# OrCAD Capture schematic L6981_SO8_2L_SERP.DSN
size Custom
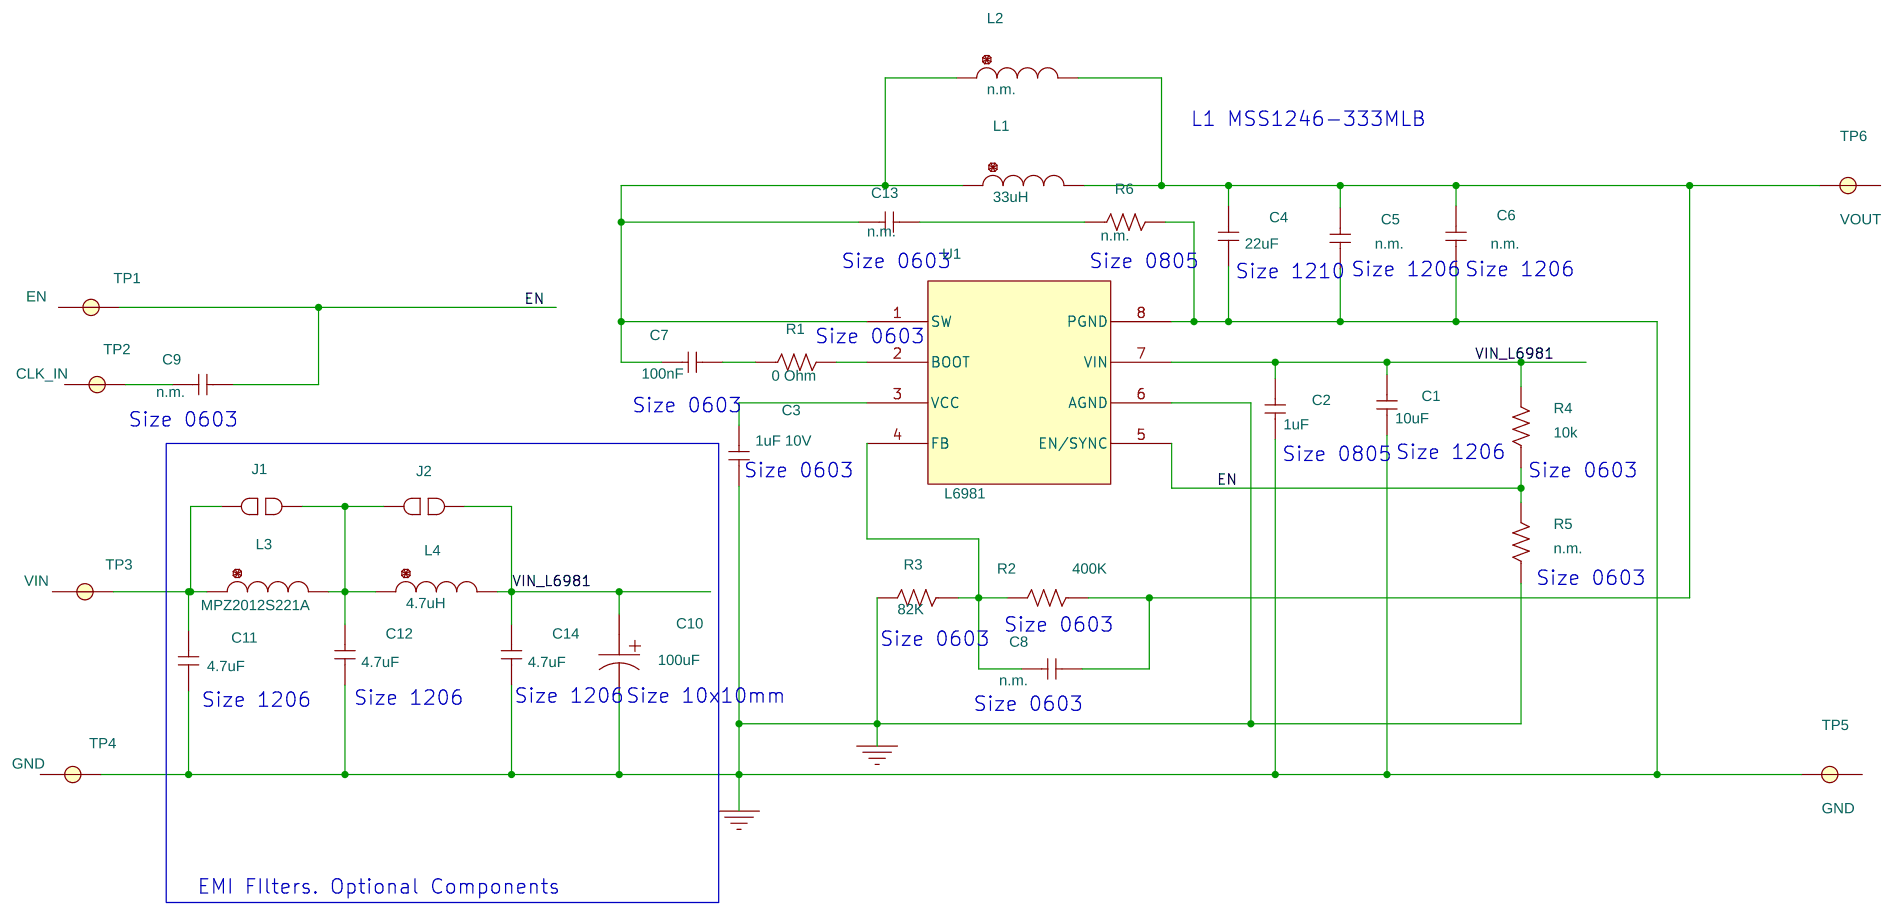
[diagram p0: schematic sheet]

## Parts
C1  10uF  [c1206]
C2  1uF  [c0805]
C3  1uF 10V  [c0603]
C4  22uF  [c1210]
C5  n.m.  [c1206]
C6  n.m.  [c1206]
C7  100nF  [c0603]
C8  n.m.  [c0603]
C9  n.m.  [c0603]
C10  100uF  [el_smd_all_G]
C11  4.7uF  [c1206]
C12  4.7uF  [c1206]
C13  n.m.  [c0603]
C14  4.7uF  [c1206]
J1  CUT 3  [PONT2_0603_no_paste]
J2  CUT 3  [PONT2_0603_no_paste]
L1  33uH  [ind_MSS1038]
L2  n.m.  [ind_XAL4040]
L3  MPZ2012S221A  [ind_mpz2012]
L4  4.7uH  [ind_XAL4040]
R1  0 Ohm  [0603]
R2  400K  [0603]
R3  82K  [0603]
R4  10k  [0603]
R5  n.m.  [0603]
R6  n.m.  [0805]
TP1  EN  [tp_torretta_13mm_f1_5]
TP2  CLK_IN  [tp_torretta_13mm_f1_5]
TP3  VIN  [tp_torretta_13mm_f1_5]
TP4  GND  [tp_torretta_13mm_f1_5]
TP5  GND  [tp_torretta_13mm_f1_5]
TP6  VOUT  [tp_torretta_13mm_f1_5]
U1  L6981  [SO8]

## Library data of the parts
C1 = C: Input capacitor; Manufacturer: TDK; Manufacturer Code: CGA5L3X5R1H106K160AB; TOLERANCE: 10%; VOLTAGE: 50
C2 = C: Input capacitor; Manufacturer: TDK; Manufacturer Code: CGA4J3X7R1H105K125AB; TOLERANCE: 10%; VOLTAGE: 50
C3 = C: Vcc capacitor; Manufacturer: Any; TOLERANCE: 10%; VOLTAGE: 10
C4 = C: Vout capacitor; Manufacturer: TDK; Manufacturer Code: CGA6P1X7R1C226M250AC; TOLERANCE: 20%; VOLTAGE: 16
C5 C6 = C: Vout capacitor; Assembly Information: Not Mounted
C7 = C: Boot capacitor; TOLERANCE: 10%; VOLTAGE: 50
C8 = C: Feed forward capacitor; Assembly Information: Not Mounted; Manufacturer: Any
C9 = C: Extern Sync. Capacitor; Assembly Information: Not Mounted; Manufacturer: Any
C10 = CAPACITOR_POL_1: El. Pi filter capacitor; Manufacturer: Panasonic; Manufacturer Code: EEHZA1H101P; TOLERANCE: 20%; VOLTAGE: 50
C11 C12 C14 = C: PI filter capacitor; Manufacturer: Murata; Manufacturer Code: GRM31CR71H475KA12L; TOLERANCE: 10%; VOLTAGE: 50
C13 = C: Snubber capacitor; Assembly Information: Not Mounted; Manufacturer: Any
J1 = CUT_3_16: Pi filter ferrite/short selector
J2 = CUT_3_16: Pi filter inductor/short selector
L1 = L: Main Inductor; Manufacturer: Coilcraft; Manufacturer Code: MSS1038T-333ML; TOLERANCE: 20%
L2 = L: Main inductor; Assembly Information: Not Mounted; Manufacturer: Coilcraft; Manufacturer Code: XAL4040
L3 = L: Pi filter ferrite bead; Manufacturer: TDK; TOLERANCE: 25%
L4 = L: Pi filter inductor; Manufacturer: Coilcraft; Manufacturer Code: XAL4030-472ME; TOLERANCE: 20%
R1 = R: Boot resistor; Manufacturer: Any
R2 = R: Feed Back HS resistor; Manufacturer: Any; TOLERANCE: 1%; Watt: 0.125
R3 = R: Feed Back LS resistor; Manufacturer: Any; TOLERANCE: 1%; Watt: 0.125
R4 = R: EN HS resistor; Manufacturer: Any; TOLERANCE: 2%; Watt: 0.125
R5 = R: EN LS resistor; Assembly Information: Not Mounted; Manufacturer: Any
R6 = R: Snubber resistor; Manufacturer: Any; Watt: 0.5
TP1-TP6 = TP: Test point; Manufacturer: ETTINGER; Manufacturer Code: 13.14.239
U1 = L6981: DC/DC Converter; Manufacturer: STMicroelectronics

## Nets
GND_POWER: C1.1 C2.1 C3.1 C4.1 C5.1 C6.1 C10.2 C11.1 C12.1 C14.1 R3.2 R5.1 R6.2 TP4.1 TP5.1 U1.6(AGND) U1.8(PGND)
VIN_L6981: C1.2 C2.2 C10.1 C14.2 J2.2 L4.2 R4.2 U1.7(VIN)
EN: C9.1 R4.1 R5.2 TP1.1 U1.5(EN/SYNC)
N00332: C7.2 C13.2 L1.1 L2.1 U1.1(SW)
N00369: R1.2 U1.2(BOOT)
N00459: C7.1 R1.1
N00575: C3.2 U1.3(VCC)
N00863: C4.2 C5.2 C6.2 C8.1 L1.2 L2.2 R2.1 TP6.1
N01548: C8.2 R2.2 R3.1 U1.4(FB)
N4101471: C12.2 J1.2 J2.1 L3.2 L4.1
N4101491: C11.2 J1.1 L3.1 TP3.1
N4112988: C13.1 R6.1
N4114079: C9.2 TP2.1

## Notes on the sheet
- L1 MSS1246-333MLB
- Size 0603
- Size 0805
- Size 1210
- Size 1206
- Size 1206
- Size 0603
- Size 0603
- Size 0603
- Size 1206
- Size 0603
- Size 0805
- Size 0603
- Size 0603
- Size 0603
- Size 0603
- Size 1206
- Size 1206
- Size 1206
- Size 10x10mm
- Size 0603
- EMI FIlters. Optional Components
